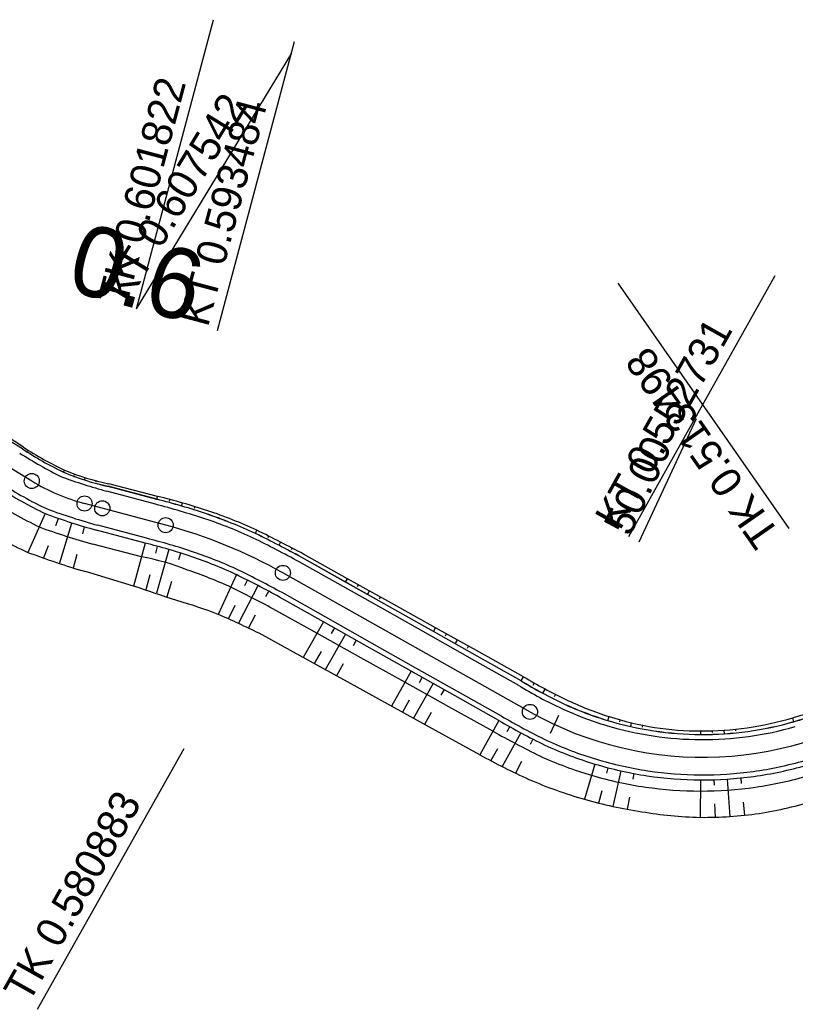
# Model space of a CAD drawing. Extents: x -481656 to -478728, y -1113199 to -1110710.
# Drawn here: x -479750.6 to -479673.5, y -1112836.4 to -1112738.2 of the extents above; entities that cross this region are included whole.
import ezdxf

# ---------------------------------------------------------------- set-up
doc = ezdxf.new("R2010")
doc.units = 0
for name, color, linetype in [('C1_HATCH_SLOPE_L', 7, 'Continuous'), ('C1_HATCH_SLOPE_R', 7, 'Continuous'), ('C1_HECTOMETRY', 7, 'Continuous'), ('C1_HLBODY', 7, 'Continuous'), ('C1_HRANA_TELESO', 7, 'Continuous'), ('C1_KORUNA', 7, 'Continuous'), ('C1_OSA', 7, 'Continuous'), ('C1_PRIKOP', 7, 'Continuous'), ('C1_STANICENI', 7, 'Continuous'), ('C1_VOZOVKA', 7, 'Continuous'), ('C1_ZPEVKRAJ', 7, 'Continuous')]:
    doc.layers.add(name, color=color, linetype=linetype)

msp = doc.modelspace()

# ---------------------------------------------------------------- linework, layer by layer
at = {"layer": 'C1_HATCH_SLOPE_L'}
for p, q in [((-479748.026, -1112787.238), (-479749.742, -1112791.086)), ((-479746.739, -1112787.764), (-479746.992, -1112788.444)), ((-479745.422, -1112788.209), (-479746.651, -1112792.264)), ((-479744.144, -1112788.563), (-479744.329, -1112789.258)), ((-479747.73, -1112790.424), (-479748.215, -1112791.723)), ((-479738.105, -1112790.173), (-479739.241, -1112794.437)), ((-479736.897, -1112790.494), (-479737.078, -1112791.172)), ((-479735.734, -1112790.814), (-479736.98, -1112795.144)), ((-479744.876, -1112791.312), (-479745.238, -1112792.669)), ((-479734.591, -1112791.158), (-479734.8, -1112791.822)), ((-479737.651, -1112793.328), (-479738.045, -1112794.804)), ((-479729.025, -1112793.302), (-479730.835, -1112797.248)), ((-479727.946, -1112793.813), (-479728.244, -1112794.423)), ((-479735.484, -1112793.994), (-479735.959, -1112795.501)), ((-479726.881, -1112794.351), (-479728.836, -1112798.106)), ((-479725.829, -1112794.916), (-479726.154, -1112795.505)), ((-479729.187, -1112796.348), (-479729.831, -1112797.664)), ((-479727.166, -1112797.334), (-479727.852, -1112798.574)), ((-479720.396, -1112797.971), (-479722.397, -1112801.528)), ((-479719.306, -1112798.584), (-479719.628, -1112799.156)), ((-479718.217, -1112799.197), (-479720.207, -1112802.735)), ((-479717.127, -1112799.81), (-479717.446, -1112800.376)), ((-479720.626, -1112800.929), (-479721.302, -1112802.131)), ((-479718.438, -1112802.14), (-479719.112, -1112803.338)), ((-479711.68, -1112802.875), (-479713.638, -1112806.354)), ((-479710.591, -1112803.488), (-479710.901, -1112804.039)), ((-479709.501, -1112804.1), (-479711.448, -1112807.56)), ((-479708.412, -1112804.713), (-479708.719, -1112805.259)), ((-479711.877, -1112805.774), (-479712.543, -1112806.957)), ((-479709.69, -1112806.984), (-479710.353, -1112808.163)), ((-479702.965, -1112807.778), (-479704.877, -1112811.178)), ((-479701.875, -1112808.391), (-479702.174, -1112808.921)), ((-479700.773, -1112809.01), (-479702.628, -1112812.36)), ((-479699.598, -1112809.634), (-479699.87, -1112810.17)), ((-479703.121, -1112810.605), (-479703.77, -1112811.759)), ((-479700.729, -1112811.86), (-479701.316, -1112813.015)), ((-479693.431, -1112812.103), (-479694.475, -1112815.584)), ((-479692.15, -1112812.463), (-479692.297, -1112813.023)), ((-479690.857, -1112812.777), (-479691.648, -1112816.311)), ((-479689.554, -1112813.044), (-479689.659, -1112813.606)), ((-479678.956, -1112813.485), (-479678.902, -1112814.024)), ((-479682.941, -1112813.675), (-479682.963, -1112817.393)), ((-479681.611, -1112813.659), (-479681.594, -1112814.208)), ((-479680.282, -1112813.595), (-479680.038, -1112817.304)), ((-479692.756, -1112814.778), (-479693.068, -1112815.972)), ((-479689.99, -1112815.383), (-479690.217, -1112816.598)), ((-479681.539, -1112816.066), (-479681.5, -1112817.375)), ((-479678.714, -1112815.873), (-479678.581, -1112817.182))]:
    msp.add_line(p, q, dxfattribs=at)
at = {"layer": 'C1_HATCH_SLOPE_R'}
for p, q in [((-479746.194, -1112783.128), (-479746.106, -1112782.931)), ((-479745.167, -1112783.548), (-479745.166, -1112783.544)), ((-479745.126, -1112783.437), (-479745.088, -1112783.335)), ((-479744.116, -1112783.903), (-479744.047, -1112783.674)), ((-479742.951, -1112784.089), (-479742.92, -1112783.973)), ((-479742.985, -1112784.215), (-479742.983, -1112784.21)), ((-479736.946, -1112785.824), (-479736.868, -1112785.532)), ((-479735.696, -1112785.99), (-479735.658, -1112785.844)), ((-479735.738, -1112786.146), (-479735.736, -1112786.142)), ((-479734.49, -1112786.489), (-479734.401, -1112786.18)), ((-479733.239, -1112786.866), (-479733.237, -1112786.862)), ((-479733.188, -1112786.704), (-479733.14, -1112786.55)), ((-479727.148, -1112789.212), (-479727.002, -1112788.893)), ((-479725.968, -1112789.771), (-479725.966, -1112789.766)), ((-479725.887, -1112789.606), (-479725.811, -1112789.45)), ((-479724.802, -1112790.36), (-479724.634, -1112790.038)), ((-479723.559, -1112790.812), (-479723.472, -1112790.655)), ((-479723.651, -1112790.978), (-479723.648, -1112790.974)), ((-479718.189, -1112794.049), (-479717.995, -1112793.705)), ((-479717.1, -1112794.662), (-479717.098, -1112794.658)), ((-479716.999, -1112794.484), (-479716.903, -1112794.313)), ((-479716.01, -1112795.275), (-479715.811, -1112794.921)), ((-479714.818, -1112795.704), (-479714.719, -1112795.53)), ((-479714.921, -1112795.888), (-479714.919, -1112795.884)), ((-479709.474, -1112798.953), (-479709.26, -1112798.572)), ((-479708.384, -1112799.566), (-479708.382, -1112799.562)), ((-479708.273, -1112799.368), (-479708.167, -1112799.18)), ((-479707.295, -1112800.179), (-479707.075, -1112799.789)), ((-479706.092, -1112800.59), (-479705.983, -1112800.397)), ((-479706.205, -1112800.791), (-479706.203, -1112800.787)), ((-479700.758, -1112803.856), (-479700.525, -1112803.441)), ((-479699.669, -1112804.469), (-479699.666, -1112804.464)), ((-479699.549, -1112804.256), (-479699.434, -1112804.052)), ((-479698.592, -1112805.074), (-479698.359, -1112804.654)), ((-479697.559, -1112805.622), (-479697.557, -1112805.618)), ((-479697.448, -1112805.402), (-479697.34, -1112805.192)), ((-479692.137, -1112807.793), (-479692.016, -1112807.39)), ((-479673.677, -1112807.901), (-479673.789, -1112807.511)), ((-479691.011, -1112808.109), (-479691.01, -1112808.104)), ((-479690.958, -1112807.908), (-479690.908, -1112807.717)), ((-479689.874, -1112808.385), (-479689.789, -1112808.005)), ((-479688.729, -1112808.62), (-479688.728, -1112808.615)), ((-479688.693, -1112808.432), (-479688.66, -1112808.253)), ((-479679.43, -1112808.818), (-479679.449, -1112808.637)), ((-479682.915, -1112809.175), (-479682.913, -1112808.821)), ((-479681.75, -1112808.976), (-479681.756, -1112808.801)), ((-479681.745, -1112809.161), (-479681.745, -1112809.156)), ((-479680.577, -1112809.105), (-479680.601, -1112808.74)), ((-479679.411, -1112809.008), (-479679.412, -1112809.003))]:
    msp.add_line(p, q, dxfattribs=at)
at = {"layer": 'C1_HECTOMETRY'}
msp.add_circle((-479742.357, -1112786.711), 0.75, dxfattribs=at)
at = {"layer": 'C1_HLBODY'}
for p, q in [((-479738.967, -1112766.916), (-479731.319, -1112738.218)), ((-479730.91, -1112769.063), (-479723.261, -1112740.365)), ((-479738.967, -1112766.916), (-479723.533, -1112741.541)), ((-479674.149, -1112788.733), (-479691.126, -1112764.364)), ((-479690.078, -1112789.499), (-479675.515, -1112763.614)), ((-479748.789, -1112836.441), (-479734.226, -1112810.556))]:
    msp.add_line(p, q, dxfattribs=at)
for centre in [(-479749.36, -1112784.004), (-479744.118, -1112786.242), (-479736.06, -1112788.389), (-479724.42, -1112793.126), (-479699.884, -1112806.929)]:
    msp.add_circle(centre, 0.75, dxfattribs=at)
at = {"layer": 'C1_HRANA_TELESO'}
for p, q in [((-479750.196, -1112780.648), (-479754.388, -1112777.918)), ((-479736.868, -1112785.532), (-479741.71, -1112784.283)), ((-479717.995, -1112793.705), (-479722.363, -1112791.27)), ((-479739.241, -1112794.437), (-479744.033, -1112793.002)), ((-479713.627, -1112796.138), (-479717.995, -1112793.705)), ((-479709.26, -1112798.572), (-479713.627, -1112796.138)), ((-479704.891, -1112801.005), (-479709.26, -1112798.572)), ((-479722.397, -1112801.528), (-479726.776, -1112799.116)), ((-479718.017, -1112803.941), (-479722.397, -1112801.528)), ((-479700.525, -1112803.441), (-479704.891, -1112801.005)), ((-479713.638, -1112806.354), (-479718.017, -1112803.941)), ((-479709.258, -1112808.766), (-479713.638, -1112806.354)), ((-479704.877, -1112811.178), (-479709.258, -1112808.766))]:
    msp.add_line(p, q, dxfattribs=at)
for centre, radius, start, end in [((-479730.055, -1112749.379), 37.194, 237.21392, 244.43398), ((-479736.46, -1112759.38), 25.45, 247.72638, 258.09615), ((-479751.698, -1112846.967), 63.2, 71.73262, 76.42847), ((-479748.836, -1112836.742), 52.596, 65.47262, 71.20221), ((-479732.257, -1112752.325), 42.523, 237.87191, 245.72143), ((-479796.647, -1112930.496), 157.804, 61.91761, 63.81052), ((-479721.645, -1112716.835), 79.389, 249.27356, 253.6202), ((-480831.692, -1116047.821), 3431.903, 71.362892, 71.438514), ((-479746.515, -1112837.588), 43.28, 68.75975, 74.4995), ((-479783.243, -1112916.464), 130.227, 64.30363, 66.26951), ((-479671.82, -1112754.737), 56.534, 239.48605, 244.3372), ((-479682.309, -1112776.586), 32.297, 244.32239, 252.50828), ((-479682.838, -1112776.468), 32.335, 286.25143, 294.4366), ((-479682.291, -1112776.525), 32.361, 252.51191, 260.69779), ((-479682.91, -1112776.466), 32.357, 278.18798, 286.37323), ((-479682.693, -1112776.428), 32.394, 261.42663, 269.61174), ((-479682.901, -1112776.438), 32.384, 269.97969, 278.16493), ((-479672.549, -1112752.594), 66.911, 241.10848, 245.79557), ((-479683.533, -1112776.127), 40.945, 246.31349, 254.50042), ((-479682.89, -1112776.389), 40.871, 253.53302, 261.7182), ((-479683.498, -1112776.597), 40.909, 278.95829, 287.14494), ((-479681.964, -1112776.491), 40.914, 260.41448, 268.60101), ((-479682.736, -1112776.426), 40.967, 269.68236, 277.86748)]:
    msp.add_arc(centre, radius, start, end, dxfattribs=at)
at = {"layer": 'C1_KORUNA'}
for p, q in [((-479750.291, -1112780.804), (-479754.563, -1112778.206)), ((-479736.946, -1112785.824), (-479741.777, -1112784.537)), ((-479738.105, -1112790.173), (-479742.936, -1112788.885)), ((-479718.189, -1112794.049), (-479722.547, -1112791.598)), ((-479713.831, -1112796.501), (-479718.189, -1112794.049)), ((-479720.396, -1112797.971), (-479724.753, -1112795.52)), ((-479709.474, -1112798.953), (-479713.831, -1112796.501)), ((-479716.038, -1112800.423), (-479720.396, -1112797.971)), ((-479705.116, -1112801.404), (-479709.474, -1112798.953)), ((-479711.68, -1112802.875), (-479716.038, -1112800.423)), ((-479700.758, -1112803.856), (-479705.116, -1112801.404)), ((-479707.322, -1112805.326), (-479711.68, -1112802.875)), ((-479702.965, -1112807.778), (-479707.322, -1112805.326))]:
    msp.add_line(p, q, dxfattribs=at)
for centre, radius, start, end in [((-479732.679, -1112754.532), 31.629, 236.16285, 244.7031), ((-479736.491, -1112760.331), 24.776, 246.94457, 257.68136), ((-479731.246, -1112752.025), 39.007, 236.75667, 244.52035), ((-479752.169, -1112846.943), 62.986, 71.32236, 76.01329), ((-479724.953, -1112724.603), 66.75, 249.77765, 254.3711), ((-479748.936, -1112836.703), 52.25, 65.35523, 71.08481), ((-479796.987, -1112929.544), 156.75, 61.64733, 63.54207), ((-479749.298, -1112837.095), 48.239, 70.8291, 76.58253), ((-479748.936, -1112836.703), 47.75, 65.35522, 71.0848), ((-479792.884, -1112921.531), 143.25, 61.60119, 63.52635), ((-479671.577, -1112754.49), 57.346, 239.4121, 244.23215), ((-479682.723, -1112776.425), 32.75, 245.10929, 253.2944), ((-479682.723, -1112776.425), 32.75, 286.03484, 294.21995), ((-479671.627, -1112754.595), 61.729, 239.49162, 244.29533), ((-479682.723, -1112776.425), 32.75, 253.2944, 261.47951), ((-479682.723, -1112776.425), 32.75, 277.84973, 286.03484), ((-479682.723, -1112776.425), 32.75, 261.47951, 269.66462), ((-479682.723, -1112776.425), 32.75, 269.66462, 277.84973), ((-479682.723, -1112776.425), 37.25, 245.1093, 253.29441), ((-479682.723, -1112776.425), 37.25, 253.29441, 261.47952), ((-479682.723, -1112776.425), 37.25, 277.84974, 286.03485), ((-479682.723, -1112776.425), 37.25, 261.47952, 269.66463), ((-479682.723, -1112776.425), 37.25, 269.66463, 277.84974)]:
    msp.add_arc(centre, radius, start, end, dxfattribs=at)
at = {"layer": 'C1_OSA'}
for p, q in [((-479749.36, -1112784.004), (-479797.961, -1112754.443)), ((-479736.06, -1112788.389), (-479744.118, -1112786.242)), ((-479699.884, -1112806.929), (-479724.42, -1112793.126))]:
    msp.add_line(p, q, dxfattribs=at)
for centre, radius, start, end in [((-479738.967, -1112766.916), 20, 238.69061, 255.07697), ((-479748.936, -1112836.703), 50, 60.63784, 75.07701), ((-479682.723, -1112776.425), 35, 240.63783, 304.86326)]:
    msp.add_arc(centre, radius, start, end, dxfattribs=at)
at = {"layer": 'C1_PRIKOP'}
for p, q in [((-479750.286, -1112780.796), (-479754.558, -1112778.197)), ((-479736.943, -1112785.815), (-479741.775, -1112784.527)), ((-479738.468, -1112791.535), (-479743.305, -1112790.27)), ((-479718.184, -1112794.041), (-479722.542, -1112791.589)), ((-479713.826, -1112796.492), (-479718.184, -1112794.041)), ((-479721.041, -1112799.119), (-479725.41, -1112796.688)), ((-479709.469, -1112798.944), (-479713.826, -1112796.492)), ((-479716.672, -1112801.55), (-479721.041, -1112799.119)), ((-479705.111, -1112801.396), (-479709.469, -1112798.944)), ((-479712.303, -1112803.982), (-479716.672, -1112801.55)), ((-479700.753, -1112803.847), (-479705.111, -1112801.396)), ((-479707.934, -1112806.413), (-479712.303, -1112803.982)), ((-479703.565, -1112808.844), (-479707.934, -1112806.413))]:
    msp.add_line(p, q, dxfattribs=at)
for centre, radius, start, end in [((-479734.274, -1112757.344), 28.396, 235.67649, 245.18844), ((-479737.125, -1112762.319), 22.689, 246.45181, 258.17534), ((-479720.135, -1112731.681), 63.621, 238.47733, 243.40256), ((-479756.31, -1112861.074), 77.712, 71.76664, 75.56885), ((-479748.936, -1112836.703), 52.26, 65.35523, 71.08481), ((-479724.296, -1112721.737), 71.12, 250.00099, 254.49743), ((-479796.996, -1112929.562), 156.78, 61.64742, 63.5421), ((-479742.544, -1112814.356), 23.182, 68.12573, 79.87363), ((-479748.72, -1112836.789), 46.375, 65.64291, 71.37256), ((-479791.022, -1112919.409), 139.16, 61.86914, 63.80503), ((-479676.036, -1112762.814), 47.903, 238.93695, 244.70696), ((-479682.723, -1112776.425), 32.74, 245.10929, 253.2944), ((-479682.723, -1112776.425), 32.74, 286.03484, 294.21995), ((-479682.723, -1112776.425), 32.74, 253.2944, 261.47951), ((-479682.723, -1112776.425), 32.74, 277.84973, 286.03484), ((-479645.849, -1112704.915), 118.88, 240.95487, 243.49397), ((-479682.723, -1112776.425), 32.74, 261.47951, 269.66462), ((-479682.723, -1112776.425), 32.74, 269.66462, 277.84973), ((-479682.914, -1112776.354), 38.43, 245.41248, 253.59771), ((-479682.922, -1112776.381), 38.401, 253.59783, 261.78305), ((-479682.922, -1112776.468), 38.314, 278.15385, 286.33908), ((-479682.926, -1112776.41), 38.372, 261.78337, 269.96859), ((-479682.926, -1112776.439), 38.343, 269.96831, 278.15353)]:
    msp.add_arc(centre, radius, start, end, dxfattribs=at)
at = {"layer": 'C1_STANICENI'}
for p, q in [((-479689.036, -1112790.032), (-479683.354, -1112777.786)), ((-479697.033, -1112807.267), (-479697.875, -1112809.082))]:
    msp.add_line(p, q, dxfattribs=at)
at = {"layer": 'C1_VOZOVKA'}
for p, q in [((-479737.075, -1112786.307), (-479741.906, -1112785.02)), ((-479737.976, -1112789.689), (-479742.807, -1112788.402)), ((-479718.434, -1112794.485), (-479722.792, -1112792.034)), ((-479714.077, -1112796.937), (-479718.434, -1112794.485)), ((-479720.15, -1112797.536), (-479724.508, -1112795.084)), ((-479715.793, -1112799.987), (-479720.15, -1112797.536)), ((-479709.719, -1112799.388), (-479714.077, -1112796.937)), ((-479705.361, -1112801.84), (-479709.719, -1112799.388)), ((-479711.435, -1112802.439), (-479715.793, -1112799.987)), ((-479707.077, -1112804.891), (-479711.435, -1112802.439)), ((-479701.003, -1112804.292), (-479705.361, -1112801.84)), ((-479702.72, -1112807.342), (-479707.077, -1112804.891))]:
    msp.add_line(p, q, dxfattribs=at)
for centre, radius, start, end in [((-479727.12, -1112744.728), 43.376, 237.30394, 243.61254), ((-479727.506, -1112732.198), 54.75, 249.81481, 254.75097), ((-479733.923, -1112756.778), 33.067, 236.09257, 245.14321), ((-479725.274, -1112725.552), 65.25, 249.783, 254.41239), ((-479768.127, -1112901.412), 119.219, 72.44127, 74.90236), ((-479748.936, -1112836.703), 51.75, 65.35523, 71.08481), ((-479751.971, -1112846.242), 58.258, 71.30256, 76.10014), ((-479796.531, -1112928.654), 155.25, 61.64255, 63.54041), ((-479748.936, -1112836.703), 48.25, 65.35523, 71.0848), ((-479793.34, -1112922.421), 144.75, 61.60669, 63.52819), ((-479679.72, -1112769.698), 40.617, 238.39935, 245.26178), ((-479682.723, -1112776.425), 33.25, 245.10929, 253.2944), ((-479667.107, -1112746.132), 70.816, 239.80832, 243.96374), ((-479682.723, -1112776.425), 33.25, 253.2944, 261.47951), ((-479682.723, -1112776.425), 33.25, 277.84973, 286.03484), ((-479682.723, -1112776.425), 33.25, 261.47951, 269.66462), ((-479682.723, -1112776.425), 33.25, 269.66462, 277.84973), ((-479682.723, -1112776.425), 36.75, 245.10929, 253.29441), ((-479682.723, -1112776.425), 36.75, 253.29441, 261.47952), ((-479682.723, -1112776.425), 36.75, 277.84974, 286.03485), ((-479682.723, -1112776.425), 36.75, 261.47952, 269.66463), ((-479682.723, -1112776.425), 36.75, 269.66463, 277.84974)]:
    msp.add_arc(centre, radius, start, end, dxfattribs=at)
at = {"layer": 'C1_ZPEVKRAJ'}
for p, q in [((-479737.075, -1112786.307), (-479741.906, -1112785.02)), ((-479737.976, -1112789.689), (-479742.807, -1112788.402)), ((-479718.434, -1112794.485), (-479722.792, -1112792.034)), ((-479714.077, -1112796.937), (-479718.434, -1112794.485)), ((-479720.15, -1112797.536), (-479724.508, -1112795.084)), ((-479715.793, -1112799.987), (-479720.15, -1112797.536)), ((-479709.719, -1112799.388), (-479714.077, -1112796.937)), ((-479705.361, -1112801.84), (-479709.719, -1112799.388)), ((-479711.435, -1112802.439), (-479715.793, -1112799.987)), ((-479707.077, -1112804.891), (-479711.435, -1112802.439)), ((-479701.003, -1112804.292), (-479705.361, -1112801.84)), ((-479702.72, -1112807.342), (-479707.077, -1112804.891))]:
    msp.add_line(p, q, dxfattribs=at)
for centre, radius, start, end in [((-479727.12, -1112744.728), 43.376, 237.30394, 243.61254), ((-479727.506, -1112732.198), 54.75, 249.81481, 254.75097), ((-479733.923, -1112756.778), 33.067, 236.09257, 245.14321), ((-479725.274, -1112725.552), 65.25, 249.783, 254.41239), ((-479768.127, -1112901.412), 119.219, 72.44127, 74.90236), ((-479748.936, -1112836.703), 51.75, 65.35523, 71.08481), ((-479751.971, -1112846.242), 58.258, 71.30256, 76.10014), ((-479796.531, -1112928.654), 155.25, 61.64255, 63.54041), ((-479748.936, -1112836.703), 48.25, 65.35523, 71.0848), ((-479793.34, -1112922.421), 144.75, 61.60669, 63.52819), ((-479679.72, -1112769.698), 40.617, 238.39935, 245.26178), ((-479682.723, -1112776.425), 33.25, 245.10929, 253.2944), ((-479667.107, -1112746.132), 70.816, 239.80832, 243.96374), ((-479682.723, -1112776.425), 33.25, 253.2944, 261.47951), ((-479682.723, -1112776.425), 33.25, 277.84973, 286.03484), ((-479682.723, -1112776.425), 33.25, 261.47951, 269.66462), ((-479682.723, -1112776.425), 33.25, 269.66462, 277.84973), ((-479682.723, -1112776.425), 36.75, 245.10929, 253.29441), ((-479682.723, -1112776.425), 36.75, 253.29441, 261.47952), ((-479682.723, -1112776.425), 36.75, 277.84974, 286.03485), ((-479682.723, -1112776.425), 36.75, 261.47952, 269.66463), ((-479682.723, -1112776.425), 36.75, 269.66463, 277.84974)]:
    msp.add_arc(centre, radius, start, end, dxfattribs=at)

# ---------------------------------------------------------------- texts
at = {"layer": 'C1_HECTOMETRY'}
msp.add_text('0.6', height=7, rotation=345.03137, dxfattribs=at).set_placement((-479746.1, -1112765.008))
at = {"layer": 'C1_HLBODY'}
for s, height, rotation, p in [('TK 0.601822', 3, 75.077, (-479739.934, -1112766.659)), ('KT 0.607542', 3, 58.69064, (-479739.822, -1112766.397)), ('KT 0.593484', 3, 75.077, (-479731.876, -1112768.807)), ('KT 0.552731', 2.999, 60.63783, (-479690.95, -1112789.009)), ('TK 0.513498', 3, 124.86326, (-479674.969, -1112789.306)), ('TK 0.580883', 2.999, 60.63783, (-479749.661, -1112835.951))]:
    msp.add_text(s, height=height, rotation=rotation, dxfattribs=at).set_placement(p)
at = {"layer": 'C1_STANICENI'}
msp.add_text('50.00', height=3, rotation=65.10929, dxfattribs=at).set_placement((-479689.944, -1112789.612))

doc.saveas('drawing.dxf')
